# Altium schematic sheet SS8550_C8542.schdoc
size 127 x 101 mm
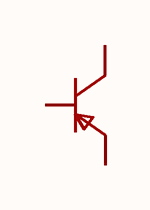
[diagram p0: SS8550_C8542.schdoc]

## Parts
Q?  ss8550 y2(range:200-350)  [SOT-23-3_L2.9-W1.3-P1.90-LS2.4-BR]  (value not drawn)

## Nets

Not connected (* = marked no-connect by the designer): Q? 1(B) 2(E) 3(C)

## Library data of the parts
Q? = ss8550 y2(range:200-350): 晶体管类型:PNP;集电极电流(Ic):1.5A;集射极击穿电压(Vceo):25V;耗散功率(Pd):300mW;直流电流增益(hFE):200;; Manufacturer: CJ(江苏长电/长晶); Symbol: SS8550_C8542; AddInBom: yes; ModelId: c62791f0466c4ae2a892c056b845b0ca; ModelName: SOT-23-3P_L2.9-W1.3-H1.0-LS2.4-P0.95; ModelTransform: 98.425,114.173,0,180,0,0,0.0005,-0.0005,0; type: PNP; Current - Collector(Ic): 1.5A; Collector - Emitter Voltage VCEO: 25V; Pd - Power Dissipation: 300mW; DC Current Gain: 200; Transition frequency(fT): 100MHz; Current - Collector Cutoff: 100nA; Vce Saturation(VCE(sat)): 500mV; Emitter-Base Voltage(Vebo): 5V; Number: 1个PNP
